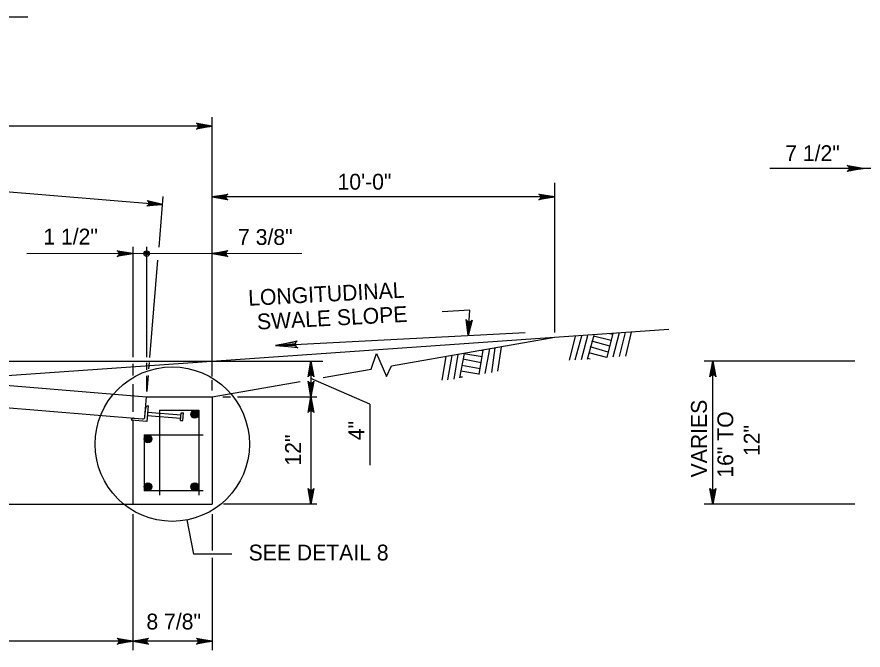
# Model space of a CAD drawing. Extents: x 2087776 to 2104538, y 970919 to 982612.
# Drawn here: x 2091278 to 2091805, y 979740 to 980133 of the extents above; entities that cross this region are included whole.
import ezdxf

# ---------------------------------------------------------------- set-up
doc = ezdxf.new("R2010")
doc.units = 0
doc.layers.add('1', color=7, linetype='Continuous')

msp = doc.modelspace()

# ---------------------------------------------------------------- linework, layer by layer
at = {"layer": '1'}
for p, q in [((2090888.24, 980133.35), (2091285.24, 980133.35)), ((2091399.85, 979909.95), (2091399.85, 980070.97)), ((2091399.85, 980065.45), (2090783.18, 980065.45)), ((2091102.59, 980038.98), (2091369.03, 980016.8)), ((2091911.48, 980039.24), (2091746.75, 980039.13)), ((2091612.78, 980030.32), (2091612.78, 979937.29)), ((2091366.84, 979990.27), (2091369.44, 980021.72)), ((2091612.78, 980021.45), (2091399.85, 980021.45)), ((2091350.54, 979990.38), (2091350.54, 979921.93)), ((2091359.11, 979990.38), (2091359.11, 979921.93)), ((2091455.68, 979986.29), (2091284.67, 979986.19)), ((2091361.15, 979921.76), (2091366.17, 979982.11)), ((2091560.13, 979951.19), (2091543, 979950.05)), ((2091559.06, 979935.3), (2091560.13, 979951.19)), ((2091232.35, 979907.76), (2091683.82, 979939.22)), ((2091439.2, 979929.06), (2091594.5, 979937.19)), ((2091629.51, 979934.95), (2091625.53, 979920.01)), ((2091633.34, 979935.1), (2091629.36, 979920.15)), ((2091637.17, 979935.32), (2091633.11, 979920.52)), ((2091648.12, 979932.32), (2091637.04, 979935.01)), ((2091649.13, 979936.7), (2091645.25, 979921.61)), ((2091649.26, 979936.03), (2091647.05, 979936.31)), ((2091652.96, 979936.99), (2091649.07, 979921.98)), ((2091656.73, 979937.14), (2091652.97, 979922.21)), ((2091660.55, 979937.35), (2091656.88, 979922.44)), ((2091511.31, 979916.59), (2091613.07, 979934.29)), ((2091625.6, 979934.64), (2091621.83, 979919.94)), ((2091647.19, 979928.77), (2091636.08, 979931.91)), ((2091556.62, 979924.19), (2091553.74, 979909.01)), ((2091568.25, 979926.33), (2091565.75, 979911.12)), ((2091568.52, 979925.86), (2091566.34, 979926.02)), ((2091572.31, 979927.08), (2091569.5, 979911.82)), ((2091575.76, 979927.72), (2091573.54, 979912.43)), ((2091579.71, 979928.18), (2091577.37, 979913.11)), ((2091645.39, 979921.76), (2091634.23, 979924.6)), ((2091646.19, 979925.07), (2091635.07, 979928.21)), ((2091092.17, 979919.43), (2091359.07, 979897.21)), ((2091164.31, 979919.43), (2091468.74, 979919.43)), ((2091461.32, 979919.43), (2091461.32, 979895.01)), ((2091545.16, 979922.33), (2091542.69, 979907.5)), ((2091548.98, 979922.95), (2091546.33, 979907.83)), ((2091552.65, 979923.51), (2091550.22, 979908.3)), ((2091567.2, 979918.41), (2091555.83, 979920.7)), ((2091567.7, 979922), (2091556.46, 979923.9)), ((2091634.9, 979920.73), (2091633.37, 979920.99)), ((2091799.5, 979919.43), (2091705.78, 979919.43)), ((2091711.29, 979830.54), (2091711.29, 979919.43)), ((2091350.54, 979917.81), (2091350.54, 979910.49)), ((2091359.11, 979918.29), (2091359.11, 979914.07)), ((2091360.56, 979914.62), (2091360.89, 979918.6)), ((2091468.82, 979909.2), (2091498.79, 979914.41)), ((2091566.62, 979914.6), (2091555.08, 979916.76)), ((2091359.11, 979910.27), (2091359.11, 979900.53)), ((2091359.39, 979900.57), (2091360.22, 979910.54)), ((2091497.83, 979892.58), (2091461.32, 979908.71)), ((2091555.66, 979909.47), (2091554.16, 979909.51)), ((2091565.76, 979911.28), (2091554.51, 979913.26)), ((2091091.52, 979905.54), (2091356.57, 979883.48)), ((2091350.54, 979905.09), (2091350.54, 979887.82)), ((2091399.85, 979901.06), (2091399.85, 979907.51)), ((2091399.85, 979897.21), (2091454.69, 979906.74)), ((2091358.07, 979884.76), (2091359.11, 979897.21)), ((2091359.07, 979897.21), (2091399.85, 979897.21)), ((2091399.85, 979897.21), (2091399.85, 979830.54)), ((2091406.53, 979897.21), (2091411.17, 979897.21)), ((2091415.54, 979897.21), (2091464.88, 979897.21)), ((2091461.32, 979897.21), (2091461.32, 979830.54)), ((2091497.83, 979892.58), (2091497.83, 979854.8)), ((2091358.07, 979884.76), (2091358.53, 979890.29)), ((2091360.03, 979891.56), (2091359.22, 979881.87)), ((2091359.71, 979887.75), (2091380.53, 979886.01)), ((2091367.21, 979888.88), (2091391.52, 979888.88)), ((2091367.21, 979888.88), (2091367.21, 979836.08)), ((2091380.25, 979882.61), (2091380.64, 979887.34)), ((2091380.64, 979887.34), (2091381.97, 979887.23)), ((2091391.52, 979888.88), (2091391.52, 979836.08)), ((2091359.22, 979881.87), (2091349.54, 979882.68)), ((2091350.54, 979882.59), (2091350.54, 979830.54)), ((2091351.04, 979883.95), (2091356.57, 979883.49)), ((2091359.54, 979885.68), (2091380.36, 979883.94)), ((2091380.25, 979882.61), (2091381.58, 979882.5)), ((2091381.58, 979882.5), (2091381.97, 979887.23)), ((2091357.49, 979873.54), (2091357.49, 979838.86)), ((2091357.49, 979873.54), (2091394.3, 979873.54)), ((2091394.3, 979838.86), (2091357.49, 979838.86)), ((2090783.18, 979830.54), (2091399.85, 979830.54)), ((2091464.88, 979830.54), (2091406.94, 979830.54)), ((2091464.88, 979830.54), (2091464.88, 979830.54)), ((2091799.5, 979830.54), (2091705.78, 979830.54)), ((2091350.54, 979824.35), (2091350.54, 979739.83)), ((2091399.85, 979824.35), (2091399.85, 979801.8)), ((2091384.13, 979820.71), (2091388.21, 979799.53)), ((2091412.12, 979799.53), (2091388.21, 979799.53)), ((2091399.85, 979797.19), (2091399.85, 979739.83)), ((2091399.85, 979745.34), (2090783.18, 979745.34))]:
    msp.add_line(p, q, dxfattribs=at)
for points in [[(2091399.85, 980065.45), (2091390.06, 980063.62), (2091390.44, 980063.88), (2091390.82, 980064.14), (2091391.01, 980064.47), (2091391.21, 980064.8), (2091391.26, 980065.13), (2091391.32, 980065.45), (2091391.26, 980065.78), (2091391.21, 980066.11), (2091391.01, 980066.44), (2091390.82, 980066.77), (2091390.44, 980067.03), (2091390.06, 980067.29), (2091399.85, 980065.45), (2091390.44, 980067.03), (2091390.82, 980066.77), (2091399.85, 980065.45), (2091391.01, 980066.44), (2091391.21, 980066.11), (2091399.85, 980065.45), (2091391.26, 980065.78), (2091391.32, 980065.45), (2091399.85, 980065.45), (2091391.26, 980065.13), (2091391.21, 980064.8), (2091399.85, 980065.45), (2091391.01, 980064.47), (2091390.82, 980064.14), (2091399.85, 980065.45), (2091390.44, 980063.88)], [(2091804.7, 980039.17), (2091794.92, 980037.33), (2091795.3, 980037.59), (2091795.67, 980037.85), (2091795.87, 980038.18), (2091796.06, 980038.51), (2091796.12, 980038.84), (2091796.17, 980039.17), (2091796.12, 980039.49), (2091796.06, 980039.82), (2091795.87, 980040.15), (2091795.67, 980040.48), (2091795.3, 980040.74), (2091794.92, 980041), (2091804.7, 980039.17), (2091795.3, 980040.74), (2091795.67, 980040.48), (2091804.7, 980039.17), (2091795.87, 980040.15), (2091796.06, 980039.82), (2091804.7, 980039.17), (2091796.12, 980039.49), (2091796.17, 980039.17), (2091804.7, 980039.17), (2091796.12, 980038.84), (2091796.06, 980038.51), (2091804.7, 980039.17), (2091795.87, 980038.18), (2091795.67, 980037.85), (2091804.7, 980039.17), (2091795.3, 980037.59)], [(2091369.03, 980016.8), (2091359.14, 980015.63), (2091359.53, 980015.87), (2091359.93, 980016.1), (2091360.14, 980016.42), (2091360.36, 980016.73), (2091360.44, 980017.06), (2091360.52, 980017.38), (2091360.48, 980017.71), (2091360.45, 980018.04), (2091360.28, 980018.38), (2091360.11, 980018.72), (2091359.75, 980019.01), (2091359.39, 980019.3), (2091369.03, 980016.8), (2091359.75, 980019.01), (2091360.11, 980018.72), (2091369.03, 980016.8), (2091360.28, 980018.38), (2091360.45, 980018.04), (2091369.03, 980016.8), (2091360.48, 980017.71), (2091360.52, 980017.38), (2091369.03, 980016.8), (2091360.44, 980017.06), (2091360.36, 980016.73), (2091369.03, 980016.8), (2091360.14, 980016.42), (2091359.93, 980016.1), (2091369.03, 980016.8), (2091359.53, 980015.87)], [(2091399.85, 980021.45), (2091409.63, 980023.29), (2091409.26, 980023.02), (2091408.88, 980022.76), (2091408.69, 980022.43), (2091408.49, 980022.11), (2091408.44, 980021.78), (2091408.38, 980021.45), (2091408.44, 980021.12), (2091408.49, 980020.79), (2091408.69, 980020.47), (2091408.88, 980020.14), (2091409.26, 980019.88), (2091409.63, 980019.62), (2091399.85, 980021.45), (2091409.26, 980019.88), (2091408.88, 980020.14), (2091399.85, 980021.45), (2091408.69, 980020.47), (2091408.49, 980020.79), (2091399.85, 980021.45), (2091408.44, 980021.12), (2091408.38, 980021.45), (2091399.85, 980021.45), (2091408.44, 980021.78), (2091408.49, 980022.11), (2091399.85, 980021.45), (2091408.69, 980022.43), (2091408.88, 980022.76), (2091399.85, 980021.45), (2091409.26, 980023.02)], [(2091612.78, 980021.45), (2091602.99, 980019.62), (2091603.37, 980019.88), (2091603.75, 980020.14), (2091603.94, 980020.47), (2091604.13, 980020.79), (2091604.19, 980021.12), (2091604.25, 980021.45), (2091604.19, 980021.78), (2091604.13, 980022.11), (2091603.94, 980022.43), (2091603.75, 980022.76), (2091603.37, 980023.02), (2091602.99, 980023.29), (2091612.78, 980021.45), (2091603.37, 980023.02), (2091603.75, 980022.76), (2091612.78, 980021.45), (2091603.94, 980022.43), (2091604.13, 980022.11), (2091612.78, 980021.45), (2091604.19, 980021.78), (2091604.25, 980021.45), (2091612.78, 980021.45), (2091604.19, 980021.12), (2091604.13, 980020.79), (2091612.78, 980021.45), (2091603.94, 980020.47), (2091603.75, 980020.14), (2091612.78, 980021.45), (2091603.37, 980019.88)], [(2091350.54, 979986.23), (2091340.76, 979984.39), (2091341.13, 979984.65), (2091341.51, 979984.91), (2091341.71, 979985.24), (2091341.9, 979985.57), (2091341.96, 979985.89), (2091342.01, 979986.22), (2091341.96, 979986.55), (2091341.9, 979986.88), (2091341.7, 979987.21), (2091341.51, 979987.53), (2091341.13, 979987.8), (2091340.76, 979988.06), (2091350.54, 979986.23), (2091341.13, 979987.8), (2091341.51, 979987.53), (2091350.54, 979986.23), (2091341.7, 979987.21), (2091341.9, 979986.88), (2091350.54, 979986.23), (2091341.96, 979986.55), (2091342.01, 979986.22), (2091350.54, 979986.23), (2091341.96, 979985.89), (2091341.9, 979985.57), (2091350.54, 979986.23), (2091341.71, 979985.24), (2091341.51, 979984.91), (2091350.54, 979986.23), (2091341.13, 979984.65)], [(2091399.85, 979986.26), (2091409.63, 979988.1), (2091409.26, 979987.84), (2091408.88, 979987.58), (2091408.69, 979987.25), (2091408.49, 979986.92), (2091408.44, 979986.59), (2091408.38, 979986.26), (2091408.44, 979985.94), (2091408.49, 979985.61), (2091408.69, 979985.28), (2091408.88, 979984.95), (2091409.26, 979984.69), (2091409.64, 979984.43), (2091399.85, 979986.26), (2091409.26, 979984.69), (2091408.88, 979984.95), (2091399.85, 979986.26), (2091408.69, 979985.28), (2091408.49, 979985.61), (2091399.85, 979986.26), (2091408.44, 979985.94), (2091408.38, 979986.26), (2091399.85, 979986.26), (2091408.44, 979986.59), (2091408.49, 979986.92), (2091399.85, 979986.26), (2091408.69, 979987.25), (2091408.88, 979987.58), (2091399.85, 979986.26), (2091409.26, 979987.84)], [(2091559.06, 979935.3), (2091557.89, 979945.19), (2091558.12, 979944.8), (2091558.36, 979944.4), (2091558.67, 979944.19), (2091558.98, 979943.97), (2091559.31, 979943.89), (2091559.63, 979943.81), (2091559.96, 979943.85), (2091560.29, 979943.88), (2091560.63, 979944.05), (2091560.97, 979944.22), (2091561.26, 979944.58), (2091561.55, 979944.94), (2091559.06, 979935.3), (2091561.26, 979944.58), (2091560.97, 979944.22), (2091559.06, 979935.3), (2091560.63, 979944.05), (2091560.29, 979943.88), (2091559.06, 979935.3), (2091559.96, 979943.85), (2091559.63, 979943.81), (2091559.06, 979935.3), (2091559.31, 979943.89), (2091558.98, 979943.97), (2091559.06, 979935.3), (2091558.67, 979944.19), (2091558.36, 979944.4), (2091559.06, 979935.3), (2091558.12, 979944.8)], [(2091452.37, 979928.16), (2091451.85, 979929.06), (2091439.2, 979929.06), (2091452.37, 979928.16), (2091453.05, 979927.62), (2091439.2, 979929.06), (2091451.62, 979930.41), (2091452.07, 979931.31), (2091439.2, 979929.06), (2091452.82, 979931.99), (2091452.07, 979931.31)], [(2091498.77, 979914.37), (2091502, 979924.24), (2091508.39, 979909.87), (2091511.31, 979916.59)], [(2091461.32, 979919.43), (2091463.16, 979909.64), (2091462.89, 979910.02), (2091462.63, 979910.4), (2091462.31, 979910.59), (2091461.98, 979910.79), (2091461.65, 979910.84), (2091461.32, 979910.9), (2091460.99, 979910.84), (2091460.66, 979910.79), (2091460.34, 979910.59), (2091460.01, 979910.4), (2091459.75, 979910.02), (2091459.49, 979909.64), (2091461.32, 979919.43), (2091459.75, 979910.02), (2091460.01, 979910.4), (2091461.32, 979919.43), (2091460.34, 979910.59), (2091460.66, 979910.79), (2091461.32, 979919.43), (2091460.99, 979910.84), (2091461.32, 979910.9), (2091461.32, 979919.43), (2091461.65, 979910.84), (2091461.98, 979910.79), (2091461.32, 979919.43), (2091462.31, 979910.59), (2091462.63, 979910.4), (2091461.32, 979919.43), (2091462.89, 979910.02)], [(2091711.29, 979919.43), (2091713.13, 979909.64), (2091712.87, 979910.02), (2091712.61, 979910.4), (2091712.28, 979910.59), (2091711.95, 979910.79), (2091711.62, 979910.84), (2091711.29, 979910.9), (2091710.96, 979910.84), (2091710.64, 979910.79), (2091710.31, 979910.59), (2091709.98, 979910.4), (2091709.72, 979910.02), (2091709.46, 979909.64), (2091711.29, 979919.43), (2091709.72, 979910.02), (2091709.98, 979910.4), (2091711.29, 979919.43), (2091710.31, 979910.59), (2091710.64, 979910.79), (2091711.29, 979919.43), (2091710.96, 979910.84), (2091711.29, 979910.9), (2091711.29, 979919.43), (2091711.62, 979910.84), (2091711.95, 979910.79), (2091711.29, 979919.43), (2091712.28, 979910.59), (2091712.61, 979910.4), (2091711.29, 979919.43), (2091712.87, 979910.02)], [(2091461.32, 979897.21), (2091459.49, 979907), (2091459.75, 979906.62), (2091460.01, 979906.24), (2091460.34, 979906.05), (2091460.66, 979905.85), (2091460.99, 979905.8), (2091461.32, 979905.74), (2091461.65, 979905.8), (2091461.98, 979905.85), (2091462.31, 979906.05), (2091462.63, 979906.24), (2091462.89, 979906.62), (2091463.16, 979907), (2091461.32, 979897.21), (2091462.89, 979906.62), (2091462.63, 979906.24), (2091461.32, 979897.21), (2091462.31, 979906.05), (2091461.98, 979905.85), (2091461.32, 979897.21), (2091461.65, 979905.8), (2091461.32, 979905.74), (2091461.32, 979897.21), (2091460.99, 979905.8), (2091460.66, 979905.85), (2091461.32, 979897.21), (2091460.34, 979906.05), (2091460.01, 979906.24), (2091461.32, 979897.21), (2091459.75, 979906.62)], [(2091461.32, 979897.21), (2091463.16, 979887.42), (2091462.89, 979887.8), (2091462.63, 979888.18), (2091462.31, 979888.37), (2091461.98, 979888.57), (2091461.65, 979888.62), (2091461.32, 979888.68), (2091460.99, 979888.62), (2091460.66, 979888.57), (2091460.34, 979888.37), (2091460.01, 979888.18), (2091459.75, 979887.8), (2091459.49, 979887.42), (2091461.32, 979897.21), (2091459.75, 979887.8), (2091460.01, 979888.18), (2091461.32, 979897.21), (2091460.34, 979888.37), (2091460.66, 979888.57), (2091461.32, 979897.21), (2091460.99, 979888.62), (2091461.32, 979888.68), (2091461.32, 979897.21), (2091461.65, 979888.62), (2091461.98, 979888.57), (2091461.32, 979897.21), (2091462.31, 979888.37), (2091462.63, 979888.18), (2091461.32, 979897.21), (2091462.89, 979887.8)], [(2091461.32, 979830.54), (2091459.49, 979840.33), (2091459.75, 979839.95), (2091460.01, 979839.57), (2091460.34, 979839.38), (2091460.66, 979839.19), (2091460.99, 979839.13), (2091461.32, 979839.07), (2091461.65, 979839.13), (2091461.98, 979839.19), (2091462.31, 979839.38), (2091462.63, 979839.57), (2091462.89, 979839.95), (2091463.16, 979840.33), (2091461.32, 979830.54), (2091462.89, 979839.95), (2091462.63, 979839.57), (2091461.32, 979830.54), (2091462.31, 979839.38), (2091461.98, 979839.19), (2091461.32, 979830.54), (2091461.65, 979839.13), (2091461.32, 979839.07), (2091461.32, 979830.54), (2091460.99, 979839.13), (2091460.66, 979839.19), (2091461.32, 979830.54), (2091460.34, 979839.38), (2091460.01, 979839.57), (2091461.32, 979830.54), (2091459.75, 979839.95)], [(2091711.29, 979830.54), (2091709.46, 979840.33), (2091709.72, 979839.95), (2091709.98, 979839.57), (2091710.31, 979839.38), (2091710.64, 979839.19), (2091710.96, 979839.13), (2091711.29, 979839.07), (2091711.62, 979839.13), (2091711.95, 979839.19), (2091712.28, 979839.38), (2091712.61, 979839.57), (2091712.87, 979839.95), (2091713.13, 979840.33), (2091711.29, 979830.54), (2091712.87, 979839.95), (2091712.61, 979839.57), (2091711.29, 979830.54), (2091712.28, 979839.38), (2091711.95, 979839.19), (2091711.29, 979830.54), (2091711.62, 979839.13), (2091711.29, 979839.07), (2091711.29, 979830.54), (2091710.96, 979839.13), (2091710.64, 979839.19), (2091711.29, 979830.54), (2091710.31, 979839.38), (2091709.98, 979839.57), (2091711.29, 979830.54), (2091709.72, 979839.95)], [(2091350.54, 979745.34), (2091340.76, 979743.51), (2091341.13, 979743.77), (2091341.51, 979744.03), (2091341.71, 979744.36), (2091341.9, 979744.68), (2091341.96, 979745.01), (2091342.01, 979745.34), (2091341.96, 979745.67), (2091341.9, 979746), (2091341.71, 979746.33), (2091341.51, 979746.65), (2091341.13, 979746.91), (2091340.76, 979747.18), (2091350.54, 979745.34), (2091341.13, 979746.91), (2091341.51, 979746.65), (2091350.54, 979745.34), (2091341.71, 979746.33), (2091341.9, 979746), (2091350.54, 979745.34), (2091341.96, 979745.67), (2091342.01, 979745.34), (2091350.54, 979745.34), (2091341.96, 979745.01), (2091341.9, 979744.68), (2091350.54, 979745.34), (2091341.71, 979744.36), (2091341.51, 979744.03), (2091350.54, 979745.34), (2091341.13, 979743.77)], [(2091350.54, 979745.34), (2091360.33, 979747.18), (2091359.95, 979746.91), (2091359.57, 979746.65), (2091359.38, 979746.33), (2091359.18, 979746), (2091359.13, 979745.67), (2091359.07, 979745.34), (2091359.13, 979745.01), (2091359.18, 979744.68), (2091359.38, 979744.36), (2091359.57, 979744.03), (2091359.95, 979743.77), (2091360.33, 979743.51), (2091350.54, 979745.34), (2091359.95, 979743.77), (2091359.57, 979744.03), (2091350.54, 979745.34), (2091359.38, 979744.36), (2091359.18, 979744.68), (2091350.54, 979745.34), (2091359.13, 979745.01), (2091359.07, 979745.34), (2091350.54, 979745.34), (2091359.13, 979745.67), (2091359.18, 979746), (2091350.54, 979745.34), (2091359.38, 979746.33), (2091359.57, 979746.65), (2091350.54, 979745.34), (2091359.95, 979746.91)], [(2091399.85, 979745.34), (2091390.06, 979743.51), (2091390.44, 979743.77), (2091390.82, 979744.03), (2091391.01, 979744.36), (2091391.21, 979744.68), (2091391.26, 979745.01), (2091391.32, 979745.34), (2091391.26, 979745.67), (2091391.21, 979746), (2091391.01, 979746.33), (2091390.82, 979746.65), (2091390.44, 979746.91), (2091390.06, 979747.18), (2091399.85, 979745.34), (2091390.44, 979746.91), (2091390.82, 979746.65), (2091399.85, 979745.34), (2091391.01, 979746.33), (2091391.21, 979746), (2091399.85, 979745.34), (2091391.26, 979745.67), (2091391.32, 979745.34), (2091399.85, 979745.34), (2091391.26, 979745.01), (2091391.21, 979744.68), (2091399.85, 979745.34), (2091391.01, 979744.36), (2091390.82, 979744.03), (2091399.85, 979745.34), (2091390.44, 979743.77)]]:
    msp.add_lwpolyline(points, dxfattribs=at)
for centre, radius in [((2091359.11, 979986.23), 1.75), ((2091359.11, 979986.23), 0.875), ((2091375.06, 979867.84), 48), ((2091389.05, 979886.41), 2.45), ((2091389.05, 979886.41), 2.27), ((2091389.05, 979886.41), 2.1), ((2091389.05, 979886.41), 1.93), ((2091389.05, 979886.41), 1.75), ((2091389.05, 979886.41), 1.58), ((2091389.05, 979886.41), 1.4), ((2091389.05, 979886.41), 1.23), ((2091389.05, 979886.41), 1.06), ((2091389.05, 979886.41), 0.883), ((2091389.05, 979886.41), 0.709), ((2091389.05, 979886.41), 0.535), ((2091389.05, 979886.41), 0.361), ((2091389.05, 979886.41), 0.188), ((2091359.95, 979871.08), 2.45), ((2091359.95, 979871.08), 2.27), ((2091359.95, 979871.08), 2.1), ((2091359.95, 979871.08), 1.93), ((2091359.95, 979871.08), 1.75), ((2091359.95, 979871.08), 1.58), ((2091359.95, 979871.08), 1.4), ((2091359.95, 979871.08), 1.23), ((2091359.95, 979871.08), 1.06), ((2091359.95, 979871.08), 0.883), ((2091359.95, 979871.08), 0.709), ((2091359.95, 979871.08), 0.535), ((2091359.95, 979871.08), 0.361), ((2091359.95, 979871.08), 0.188), ((2091359.96, 979841.31), 2.45), ((2091359.96, 979841.31), 2.27), ((2091359.96, 979841.31), 2.1), ((2091359.96, 979841.31), 1.93), ((2091359.96, 979841.31), 1.75), ((2091359.96, 979841.31), 1.58), ((2091359.96, 979841.31), 1.4), ((2091359.96, 979841.31), 1.23), ((2091359.96, 979841.31), 1.06), ((2091359.96, 979841.31), 0.883), ((2091359.96, 979841.31), 0.709), ((2091359.96, 979841.31), 0.535), ((2091359.96, 979841.31), 0.361), ((2091359.96, 979841.31), 0.188), ((2091389.1, 979841.37), 2.45), ((2091389.1, 979841.37), 2.27), ((2091389.1, 979841.37), 2.1), ((2091389.1, 979841.37), 1.93), ((2091389.1, 979841.37), 1.75), ((2091389.1, 979841.37), 1.58), ((2091389.1, 979841.37), 1.4), ((2091389.1, 979841.37), 1.23), ((2091389.1, 979841.37), 1.06), ((2091389.1, 979841.37), 0.883), ((2091389.1, 979841.37), 0.709), ((2091389.1, 979841.37), 0.535), ((2091389.1, 979841.37), 0.361), ((2091389.1, 979841.37), 0.188)]:
    msp.add_circle(centre, radius, dxfattribs=at)
for centre, start, end in [((2091359.91, 979890.17), 85.2368, 175.2368), ((2091350.92, 979882.56), 85.2368, 175.2368), ((2091356.68, 979884.87), 265.2368, 355.2368)]:
    msp.add_arc(centre, 1.39, start, end, dxfattribs=at)

# ---------------------------------------------------------------- texts
for s, height, p in [('7 1/2"', 9.843, (2091756.28, 980043.72)), ('10\'-0"', 9.843, (2091477.84, 980025.99)), ('1 1/2"', 9.843, (2091294.85, 979991.9)), ('SEE DETAIL 8', 9.8425, (2091422.55, 979795.52))]:
    msp.add_text(s, height=height, dxfattribs=at).set_placement(p)
for s, height, rotation, p in [('7 3/8"', 9.843, 360, (2091415.96, 979991.63)), ('LONGITUDINAL', 9.8425, 2.9966, (2091422.53, 979953.79)), ('SWALE SLOPE', 9.8425, 2.9966, (2091428.01, 979938.97)), ('VARIES', 9.843, 90, (2091707.54, 979847.14)), ('16" TO', 9.843, 90, (2091723.94, 979846.95)), ('4"', 9.843, 90, (2091494.43, 979870.26)), ('12"', 9.843, 90, (2091740.35, 979860.39)), ('12"', 9.843, 90, (2091455.07, 979854.5)), ('8 7/8"', 9.843, 360, (2091358.97, 979752.63))]:
    msp.add_text(s, height=height, rotation=rotation, dxfattribs=at).set_placement(p)

doc.saveas('drawing.dxf')
